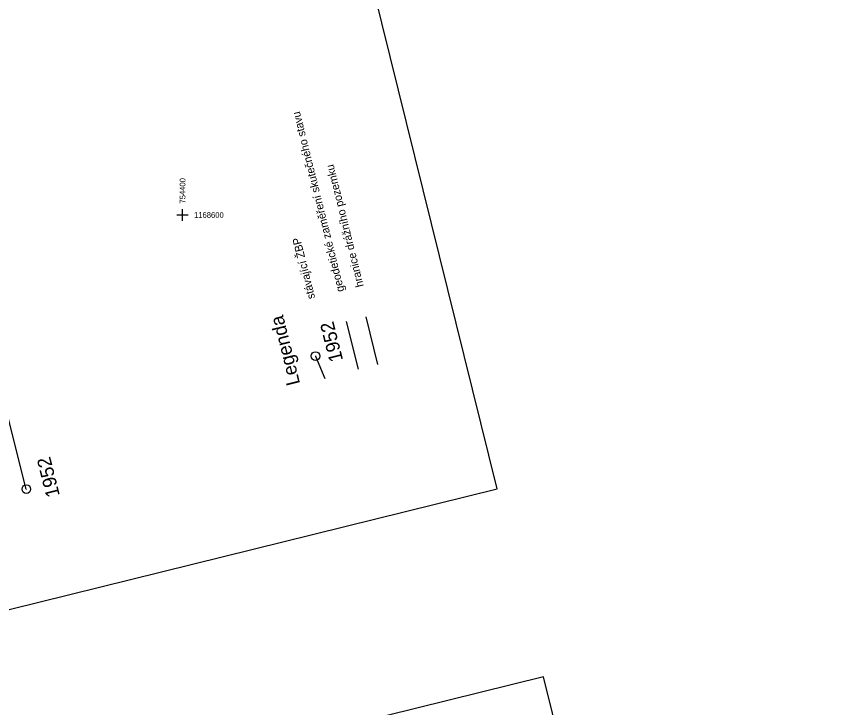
# Model space of a CAD drawing. Extents: x -754679 to -754173, y -1169241 to -1168288.
# Drawn here: x -754458.2 to -754172.8, y -1168772.6 to -1168530.4 of the extents above; entities that cross this region are included whole.
import ezdxf

# ---------------------------------------------------------------- set-up
doc = ezdxf.new("R2010")
doc.units = 0
for name, color, linetype in [('Default', 7, 'Continuous'), ('Vrstva 1', 7, 'Continuous'), ('Vrstva 2', 7, 'Continuous'), ('Vrstva 24', 7, 'Continuous'), ('Vrstva 27', 7, 'Continuous'), ('Vrstva 61', 7, 'Continuous'), ('Vrstva 63', 7, 'Continuous')]:
    doc.layers.add(name, color=color, linetype=linetype)

msp = doc.modelspace()

# ---------------------------------------------------------------- linework, layer by layer
at = {"layer": 'Default'}
for points in [[(-754400, -1168602), (-754400, -1168600), (-754400, -1168598)], [(-754402, -1168600), (-754400, -1168600), (-754398, -1168600)]]:
    msp.add_lwpolyline(points, dxfattribs=at)
at = {"layer": 'Vrstva 1'}
msp.add_line((-754454.68, -1168695.98), (-754454.68, -1168695.98), dxfattribs=at)
at = {"layer": 'Vrstva 24'}
msp.add_line((-754331.66, -1168652.34), (-754335.79, -1168635.66), dxfattribs=at)
at = {"layer": 'Vrstva 27'}
msp.add_line((-754338.45, -1168654.02), (-754342.58, -1168637.34), dxfattribs=at)
at = {"layer": 'Vrstva 61'}
for points in [[(-754578.24, -1168767.26), (-754289.93, -1168695.96), (-754390.75, -1168288.24), (-754679.07, -1168359.54)], [(-754461.15, -1169240.8), (-754172.83, -1169169.5), (-754273.65, -1168761.78), (-754561.97, -1168833.08)]]:
    msp.add_lwpolyline(points, dxfattribs=at)
at = {"layer": 'Vrstva 63'}
for p, q in [((-754353.48, -1168649.3), (-754353.47, -1168649.5)), ((-754454.78, -1168695.98), (-754454.58, -1168695.98))]:
    msp.add_line(p, q, dxfattribs=at)
for points in [[(-754454.68, -1168695.98), (-754495.29, -1168534.73), (-754520.59, -1168389.67)], [(-754353.48, -1168649.4), (-754350.16, -1168657.27)]]:
    msp.add_lwpolyline(points, dxfattribs=at)
for centre in [(-754353.48, -1168649.4), (-754454.68, -1168695.98)]:
    msp.add_circle(centre, 1.51, dxfattribs=at)

# ---------------------------------------------------------------- texts
at = {"layer": 'Default'}
msp.add_text('754400', height=2, rotation=90, dxfattribs=at).set_placement((-754399, -1168596))
msp.add_text('1168600', height=2, dxfattribs=at).set_placement((-754396, -1168601))
at = {"layer": 'Vrstva 2'}
for p in [(-754343.8, -1168650.81), (-754442.91, -1168698.2)]:
    msp.add_text('1952', height=4.8, rotation=104.1384, dxfattribs=at).set_placement(p)
at = {"layer": 'Vrstva 27'}
for s, height, p in [('geodetické zaměření skutečného stavu', 2.8, (-754343.38, -1168626.57)), ('hranice drážního pozemku', 2.8, (-754336.58, -1168624.89)), ('stávající ŽBP', 2.8, (-754353.57, -1168629.09)), ('Legenda', 4.8, (-754358.84, -1168659.06))]:
    msp.add_text(s, height=height, rotation=103.9106, dxfattribs=at).set_placement(p)

doc.saveas('drawing.dxf')
